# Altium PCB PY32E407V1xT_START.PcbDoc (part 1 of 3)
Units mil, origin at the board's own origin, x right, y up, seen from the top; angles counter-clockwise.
Board outline 1968.43 x 4717 mil, 2 copper layers (Top Layer, Bottom Layer), stack 21 mil thick; 210 components, 217 nets, 824 pads, 371 vias.
Unrouted connection lines stored in the file: 1.
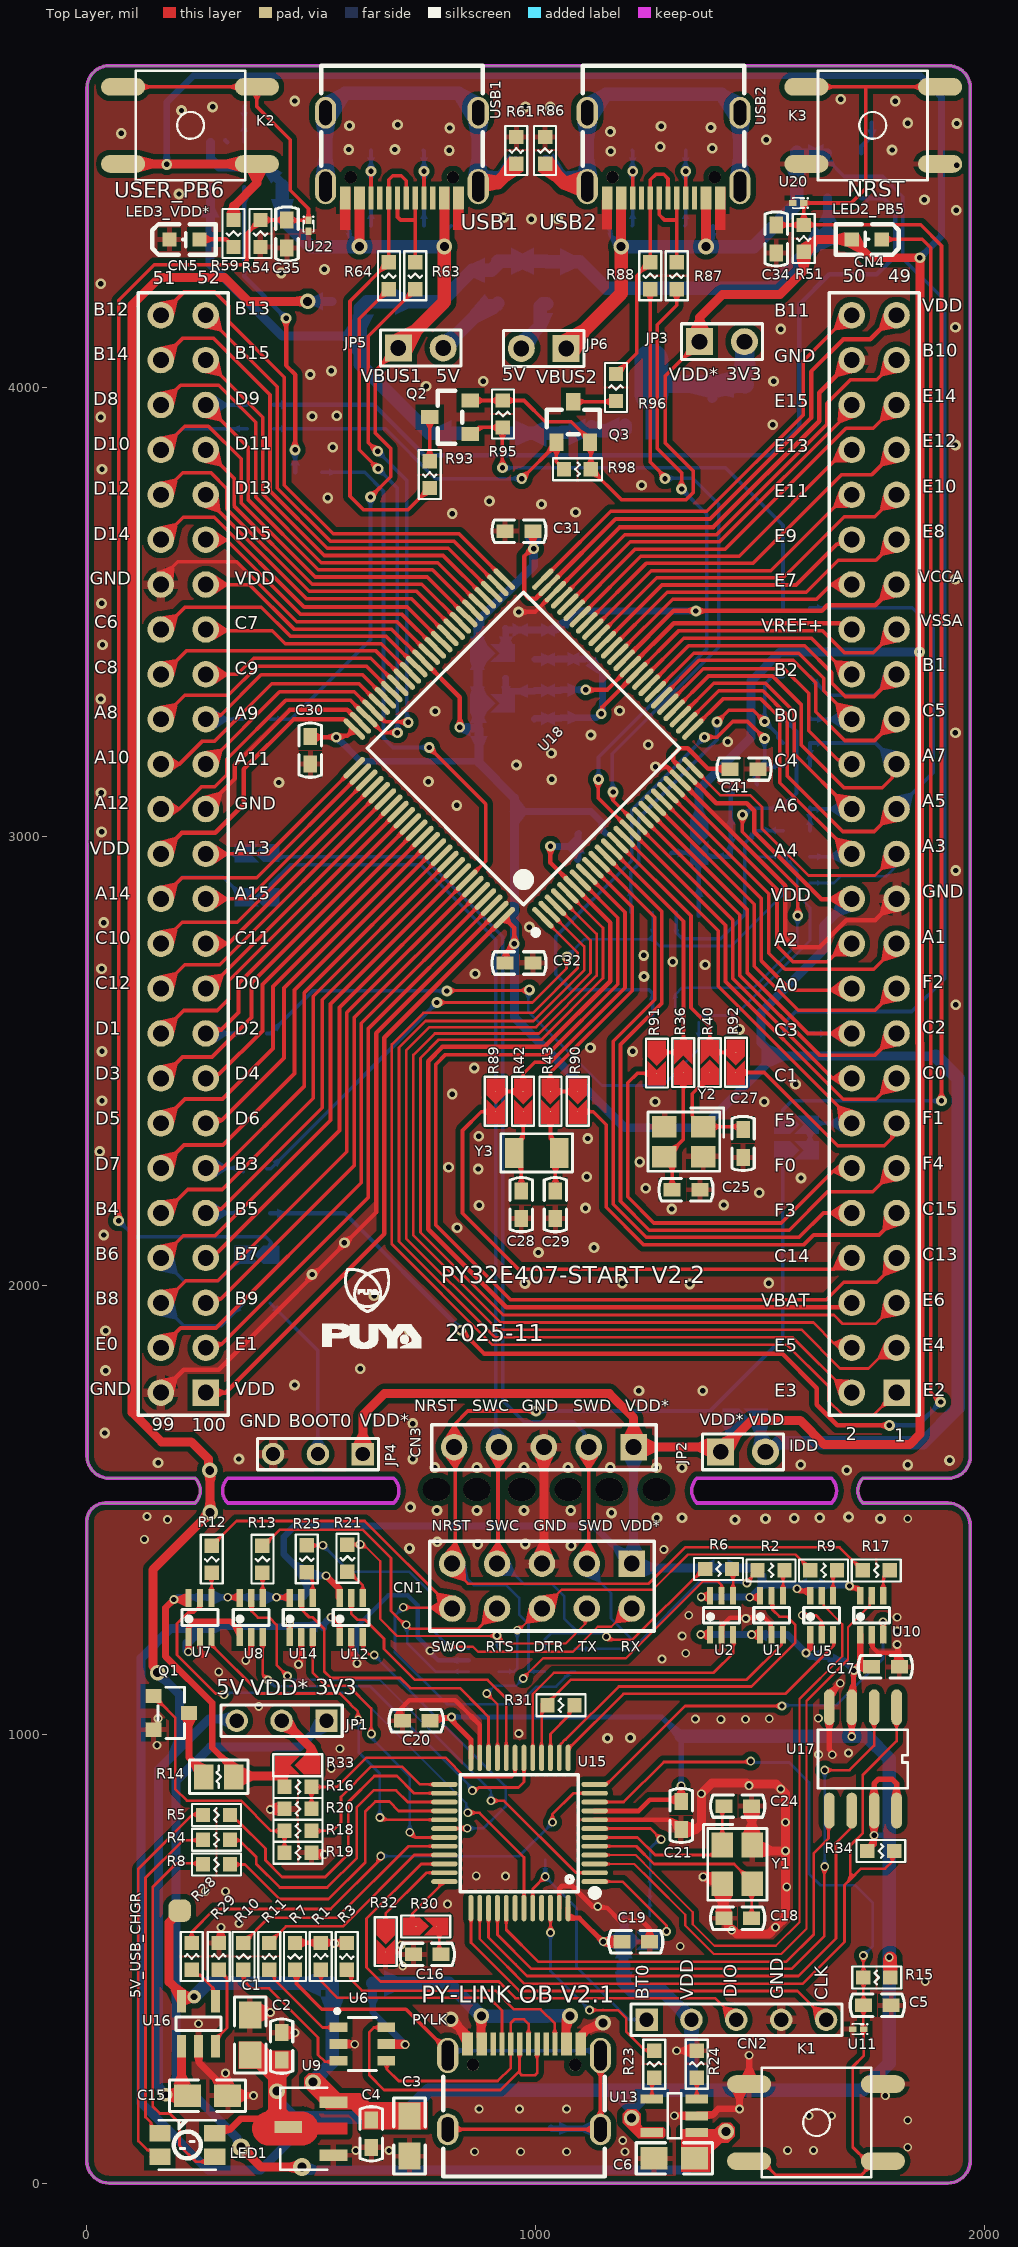
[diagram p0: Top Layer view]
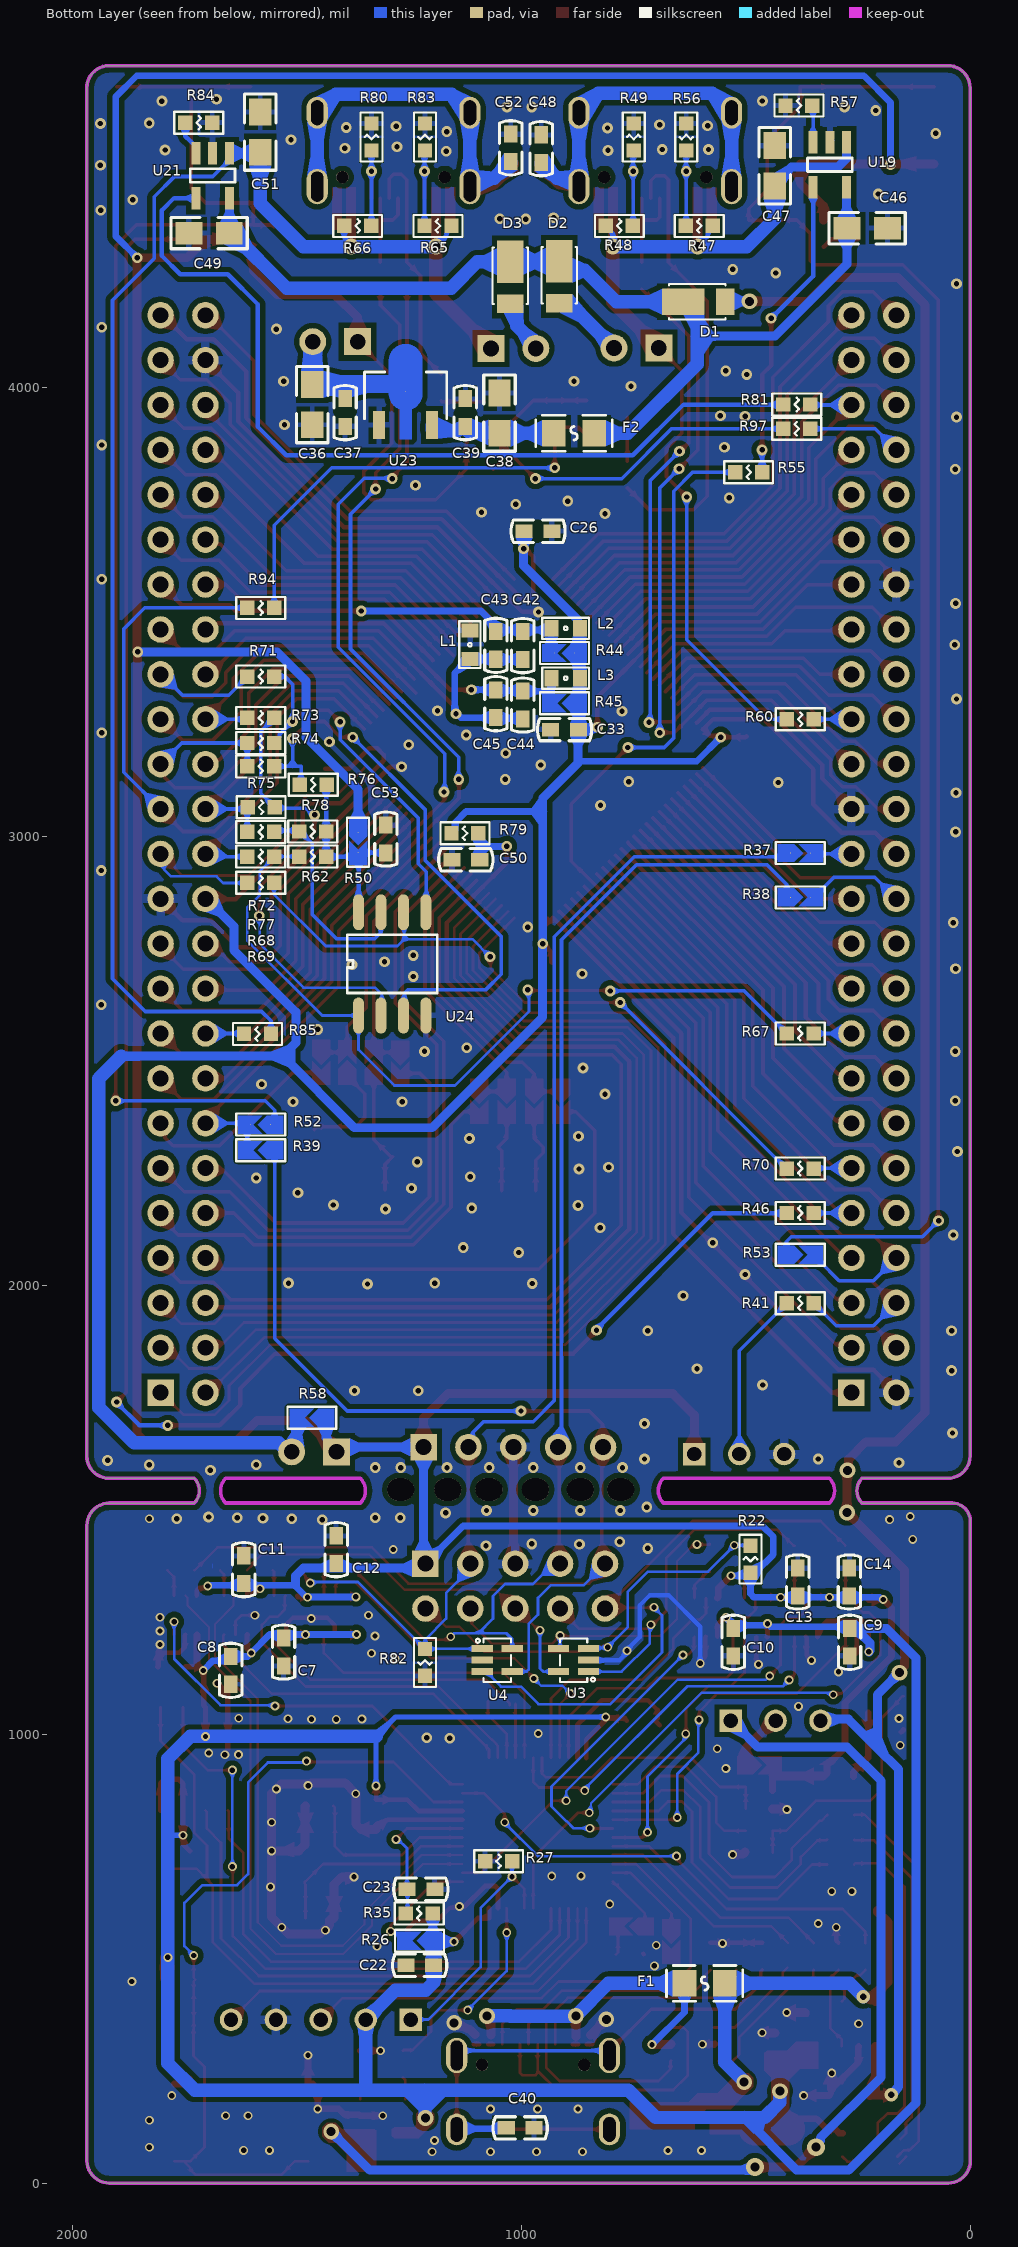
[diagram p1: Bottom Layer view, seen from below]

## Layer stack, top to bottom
Top Solder: solder mask 0.4, Solder Resist, Dk 3.5
Top Layer: signal copper 1.4
Dielectric 2: prepreg 2.8, Composite dielectric, Dk 4.1
Dielectric 1: prepreg 12.6, Composite dielectric, Dk 4.1
Dielectric 3: prepreg 2.8, Composite dielectric, Dk 4.1
Bottom Layer: signal copper 1.4
Bottom Solder: solder mask 0.4, Solder Resist, Dk 3.5

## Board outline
0,50 ccw(c50,50) 50,0 1918,0 ccw(c1918,50) 1968,50 1968,1465 ccw(c1918,1465) 1918,1515 1729,1515 cw(c1756.5,1542.5) 1729,1570 1918.43,1570 ccw(c1918.43,1620) 1968.43,1620 1968.43,4667 ccw(c1918.43,4667) 1918.43,4717 50.57,4717 ccw(c50.57,4667) 0.57,4667 0.57,1620 ccw(c50.57,1620) 50.57,1570 241.5,1570 cw(c214,1542.5) 241.5,1515 41,1515 ccw(c41,1474) 0,1474
cut-out: 1359,1515 cw(c1386.5,1542.5) 1359,1570 1659,1570 cw(c1631.5,1542.5) 1659,1515
cut-out: 314,1515 cw(c341.5,1542.5) 314,1570 684,1570 cw(c656.5,1542.5) 684,1515
cut-out: 314,1515 cw(c341.5,1542.5) 314,1570 684,1570 cw(c656.5,1542.5) 684,1515 664,1515
cut-out: 1359,1515 cw(c1386.5,1542.5) 1359,1570 1659,1570 cw(c1631.5,1542.5) 1659,1515

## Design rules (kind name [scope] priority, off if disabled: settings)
Clearance polygon [InPolygon] p1: gap=12 ignorepadtopadclearanceinfootprint=TRUE
Clearance [All] p2: gap=8 ignorepadtopadclearanceinfootprint=TRUE
HoleToHoleClearance [All] p1: gap=1 allowstackedmicrovias=TRUE
MinimumSolderMaskSliver [All] p1: minsoldermaskwidth=0
PlaneClearance [All] p1: clearance=8
PlaneConnect [All] p1: planeconnectstyle=Direct reliefexpansion=20 reliefentries=4 reliefconductorwidth=10 reliefairgap=10
PolygonConnect [All] p1: thpad.connectstyle=Relief thpad.reliefconductorwidth=20 thpad.reliefentries=4 thpad.polygonreliefangle="90 Angle" thpad.airgapwidth=10 smdpad.connectstyle=Relief smdpad.reliefconductorwidth=12 smdpad.reliefentries=4 smdpad.polygonreliefangle="90 Angle" smdpad.airgapwidth=10 via.connectstyle=Direct via.reliefconductorwidth=10 via.reliefentries=4 via.polygonreliefangle="90 Angle" via.airgapwidth=10
RoutingVias [All] p1: holewidth=28 width=50 viastyle="Through Hole" minholewidth=28 minwidth=50 maxholewidth=28 maxwidth=50
SilkToSilkClearance [All] p1: silktosilkclearance=0
SilkToSolderMaskClearance [IsPad] p1: minsilkscreentomaskgap=0 clearancetoexposedcopper=TRUE
SolderMaskExpansion [All] p1: expansion=4 istentingtop=FALSE
UnRoutedNet [All] p1: checkbadconnections=TRUE
Width [All] p1: maxlimit=100 minlimit=5 preferedwidth=8
23 further rules are at their usual default settings.

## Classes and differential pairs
component class PY32E407V1xT_USB: C46 C47 C48 C49 C51 C52 Q2 Q3 R47 R48 R49 R55 R56 R57 R60 R61 R63 R64 R65 R66 R80 R81 R83 R84 R85 R86 R87 R88 R93 R94 R95 R96 R97 R98 U19 U21 USB1 USB2
component class PY32E407V1xT_START: C25 C26 C27 C28 C29 C30 C31 C32 C33 C34 C35 C36 C37 C38 C39 C41 C42 C43 C44 C45 C50 C53 CN3 CN4 CN5 D1 D2 D3 F2 "IDD Test" JP2 JP3 JP4 JP5 JP6 K2 K3 L1 L2 L3 LED2_PB5 LED3_VDD* PF8 R36 R37 R38 R39 R40 R41 R42 R43 R44 R45 R46 R50 R51 R52 R53 R54 R58 R59 R62 R67 R68 R69 R70 R71 R72 R73 R74 R75 R76 R77 R78 R79 R89 R90 R91 R92 ss U18 U20 U22 U23 U24 Y2 Y3
component class PY32F403C1xT_LINK: 5V_USB_CHGR C1 C2 C3 C4 C5 C6 C7 C8 C9 C10 C11 C12 C13 C14 C15 C16 C17 C18 C19 C20 C21 C22 C23 C24 C40 CN1 CN2 F1 JP1 K1 LED1 PYLK Q1 R1 R2 R3 R4 R5 R6 R7 R8 R9 R10 R11 R12 R13 R14 R15 R16 R17 R18 R19 R20 R21 R22 R23 R24 R25 R26 R27 R28 R29 R30 R31 R32 R33 R34 R35 R82 ss U1 U2 U3 U4 U5 U6 U7 U8 U9 U10 U11 U12 U13 U14 U15 U16 U17 Y1

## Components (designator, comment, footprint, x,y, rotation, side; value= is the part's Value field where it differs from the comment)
5V_USB_CHGR "TP_SIN" TP_SIN 207,607 r90 top
C1 "10uF" C0805 364,330 r270 top
C2 "100nF" C0603 434,305 r270 top
C3 "10uF" C0805 719,105 r90 top
C4 "100nF" C0603 634,110 r90 top
C5 "100nF" C0603 1761,396 r180 top
C6 "10uF" C0805 1309,55 r0 top
C7 "100nF" C0603 1530,1183 r90 bottom value=104
C8 "100nF" C0603 1647.9,1142.3 r90 bottom value=104
C9 "100nF" C0603 269.2,1204.9 r90 bottom value=104
C10 "100nF" C0603 528,1204.9 r90 bottom value=104
C11 "100nF" C0603 1618.4,1366.6 r270 bottom value=104
C12 "100nF" C0603 1412.8,1411.1 r270 bottom value=104
C13 "100nF" C0603 384.5,1339.2 r270 bottom value=104
C14 "100nF" C0603 269.5,1339.2 r270 bottom value=104
C15 "10uF" C0805 269,195 r180 top
C16 "100nF" C0603 758.59,509.5 r0 top
C17 "100nF" C0603 1779,1150 r180 top value=104
C18 "22pF" C0603 1450.12,590 r0 top
C19 "100nF" C0603 1222.87,537.59 r180 top value=104
C20 "100nF" C0603 734,1030 r0 top value=104
C21 "100nF" C0603 1324.12,819 r90 top value=104
C22 "100nF" C0603 1226.74,485.58 r180 bottom value=104
C23 "100nF" C0603 1224.12,655 r0 bottom value=104
C24 "22pF" C0603 1450.12,840 r180 top
C25 "22pF" C0603 1335,2212.99 r180 top
C26 "10uF" C0603 963,3680 r0 bottom
C27 "22pF" C0603 1462,2315.99 r90 top
C28 "22pF" C0603 968,2179.5 r270 top
C29 "22pF" C0603 1044,2179.5 r90 top
C30 "100nF" C0603 498,3192 r90 top
C31 "100nF" C0603 963,3680 r0 top
C32 "100nF" C0603 963,2718 r180 top
C33 "100nF" C0603 904,3238 r180 bottom
C34 "100nF" C0603 1536,4331 r90 top
C35 "100nF" C0603 446,4342 r90 top
C36 "10uF" C0805 1466,3962 r90 bottom
C37 "100nF" C0603 1393,3944 r90 bottom
C38 "10uF" C0805 1049,3943 r270 bottom
C39 "100nF" C0603 1125,3944 r270 bottom
C40 "4.7nF" C0603 1003,123 r0 bottom
C41 "100nF" C0603 1464,3150 r180 top
C42 "1uF" C0603 997,3425 r90 bottom
C43 "100nF" C0603 1057,3425.57 r90 bottom
C44 "1uF" C0603 997,3292.5 r90 bottom
C45 "100nF" C0603 1057,3295.5 r90 bottom
C46 "10uF" C0805 230,4355 r0 bottom
C47 "10uF" C0805 436,4494 r270 bottom
C48 "4.7nF" C0603 956,4532 r270 bottom
C49 "10uF" C0805 1696,4344 r180 bottom
C50 "100nF" C0603 1124,2948 r180 bottom
C51 "10uF" C0805 1582,4569 r270 bottom
C52 "4.7nF" C0603 1024,4534 r270 bottom
C53 "100nF" C0603 1302,2994 r270 bottom value=104
CN1 "2X5P" HDR2X5 1214,1380 r180 top
CN2 "CON5" CON5 1247,364 r0 top
CN3 "Header 5" HDR1X5 1218.26,1639.56 r180 top
CN4 "2X25P" HDR2X25 1804,1761 r90 top locked
CN5 "2X25P" HDR2X25 265,1761 r90 top locked
D1 "DFLS130L-7" POWERDI-123_L2.8-W1.8-LS3.7-RD 593,4191 r180 bottom
D2 "DFLS130L-7" POWERDI-123_L2.8-W1.8-LS3.7-RD 916,4234 r270 bottom
D3 "DFLS130L-7" POWERDI-123_L2.8-W1.8-LS3.7-RD 1025,4233 r270 bottom
F1 "JK-SMD0805-050-16V" F0805 592,445 r180 bottom
F2 "JK-SMD0805-050-16V" F0805 883,3898 r0 bottom
JP1 "CON3" CON3 534,1030 r180 top
JP2 "CON2" CON2 1412,1629.13 r0 top
JP3 "CON2" CON2 1365,4102 r0 top
JP4 "CON3" CON3 615,1624.13 r180 top
JP5 "CON2" CON2 694,4088 r0 top
JP6 "CON2" CON2 1068,4087 r180 top
K1 "TS-KG02S" Switch 1626.55,134.7 r180 top
K2 "TS-KG02S" Switch 232,4583.7 r180 top
K3 "TS-KG02S" Switch 1750,4584 r0 top
L1 "BEAD" L0603 1115,3427 r90 bottom value=600R@100MHz
L2 "BEAD" L0603 901.52,3463.5 r0 bottom value=600R@100MHz
L3 "BEAD" L0603 901.52,3352.5 r0 bottom value=600R@100MHz
LED1 "MHPA3528RGBCT" LED-ARRAY-SMD_4P-L3.5-W2.8-TL 224,85 r0 top
LED2_PB5 "GREEN" 0603_LED 1723,4331 r180 top
LED3_VDD* "RED" 0603_LED 232,4329 r0 top
PYLK "KH-TYPE-C-16P" USB-C-SMD_KH-TYPE-C-16P 974.2,214.81 r0 top locked
Q1 "2302" SOT23 188.37,1047.4 r90 top value=SI2302
Q2 "2301" "SOT23 2301" 854.55,3896.6 r0 top value=SI2301
Q3 "2301" "SOT23 2301" 1046.2,3878 r270 top value=SI2301
R1 "5.1K" R0603 521.49,504.99 r270 top
R2 "27R" R0603 1524.21,1365 r180 top
R3 "5.1K" R0603 579,505 r90 top
R4 "680R" R0603 289,765 r0 top
R5 "680R" R0603 289,820 r0 top
R6 "27R" R0603 1407.39,1368.1 r180 top
R7 "1M" R0603 464,505 r90 top
R8 "680R" R0603 289,710 r0 top
R9 "27R" R0603 1641.35,1365 r180 top
R10 "27R" R0603 349,505 r90 top
R11 "27R" R0603 406.5,505 r90 top
R12 "27R" R0603 278.66,1390.08 r90 top
R13 "27R" R0603 391.3,1390.1 r90 top
R14 "100R" R0805 294,905 r0 top
R15 "10K" R0603 1759.77,458 r0 top
R16 "20K" R0603 470.52,882.61 r180 top
R17 "27R" R0603 1758.49,1365 r180 top
R18 "100R" R0603 470.53,784.78 r0 top
R19 "100K" R0603 470.52,735.88 r180 top
R20 "10K" R0603 470.53,833.69 r0 top
R21 "27R" R0603 580.63,1392.11 r90 top
R22 "4.7K" R0603 490,1390 r270 bottom
R23 "4.7K" R0603 1264,265 r270 top
R24 "16K" R0603 1359,265 r270 top
R25 "27R" R0603 490.2,1390.7 r90 top
R26 "0R" JP2_SMD 1227.34,539.83 r180 bottom
R27 "10K" R0603 1051,717.08 r0 bottom
R28 "4.7K" R0603 234,505 r270 top
R29 "16K" R0603 294,505 r270 top
R30 "0R" JP2_SMD 755.21,571.75 r180 top
R31 "680R" R0603 1056.46,1064.37 r0 top
R32 "0R" JP2_SMD 666,538 r90 top
R33 "0R" JP2_SMD 470,931 r0 top
R34 "100K" R0603 1769,740 r180 top
R35 "10K" R0603 1227.6,600.62 r180 bottom
R36 "0R" JP2_SMD 1329,2496 r270 top
R37 "100R" JP2_SMD 379,2963 r0 bottom
R38 "100R" JP2_SMD 379,2864 r0 bottom
R39 "0R" JP2_SMD 1581.01,2301 r180 bottom
R40 "0R" JP2_SMD 1388,2495.99 r270 top
R41 "10K" R0603 379,1960 r180 bottom
R42 "0R" JP2_SMD 972,2410 r90 top
R43 "0R" JP2_SMD 1033,2410 r90 top
R44 "0R/NC" JP2_SMD 904,3408.5 r180 bottom
R45 "0R/NC" JP2_SMD 904,3296.5 r180 bottom
R46 "680R" R0603 379,2161 r180 bottom
R47 "56K/NC" R0603 604,4359.99 r180 bottom
R48 "56K/NC" R0603 782,4360 r0 bottom
R49 "5.1K" R0603 750,4558 r270 bottom
R50 "0R" JP2_SMD 1363.97,2987.03 r90 bottom
R51 "10K" R0603 1597,4332 r90 top
R52 "0R" JP2_SMD 1581.01,2358 r180 bottom
R53 "0R" JP2_SMD 379,2068 r0 bottom
R54 "1.5K" R0603 387,4343 r90 top
R55 "4.7K" R0603 494,3811 r180 bottom
R56 "5.1K" R0603 633,4558.01 r90 bottom
R57 "16K" R0603 382,4628 r180 bottom
R58 "0R" JP2_SMD 1467,1705 r180 bottom
R59 "680R" R0603 327,4343 r90 top
R60 "1K" R0603 379,3261 r0 bottom
R61 "1M" R0603 957,4528 r90 top
R62 "100K" R0603 1465,2954.99 r180 bottom
R63 "22R" R0603 732,4249 r90 top
R64 "22R" R0603 673,4249 r90 top
R65 "56K/NC" R0603 1186,4360 r180 bottom
R66 "56K/NC" R0603 1365,4360 r0 bottom
R67 "0R" R0603 379,2561 r180 bottom
R68 "0R/NC" R0603 1581.01,2955 r0 bottom
R69 "0R" R0603 1581.01,2897 r0 bottom
R70 "0R/NC" R0603 379,2260 r180 bottom
R71 "0R" R0603 1581.01,3356 r0 bottom
R72 "0R/NC" R0603 1580,3065 r0 bottom
R73 "0R" R0603 1581.01,3264 r0 bottom
R74 "0R/NC" R0603 1581.01,3208 r0 bottom
R75 "0R" R0603 1581.01,3156 r0 bottom
R76 "0R/NC" R0603 1464,3115 r180 bottom
R77 "0R" R0603 1581,3010 r0 bottom
R78 "0R/NC" R0603 1465,3011 r180 bottom
R79 "0R" R0603 1126,3007 r180 bottom
R80 "5.1K" R0603 1334,4558 r270 bottom
R81 "4.7K" R0603 387,3962 r0 bottom
R82 "1M" R0603 1215,1160 r90 bottom
R83 "5.1K" R0603 1215,4558.01 r90 bottom
R84 "16K" R0603 1719,4590 r0 bottom
R85 "1K" R0603 1588,2560 r180 bottom
R86 "1M" R0603 1021,4528 r90 top
R87 "22R" R0603 1314,4249 r90 top
R88 "22R" R0603 1255,4249 r90 top
R89 "0R" JP2_SMD 911,2410 r90 top
R90 "0R" JP2_SMD 1094,2410 r90 top
R91 "0R" JP2_SMD 1270,2495 r90 top
R92 "0R" JP2_SMD 1446,2497 r90 top
R93 "1.5K" R0603 764,3806 r90 top
R94 "100" R0603 1581.01,3509 r0 bottom
R95 "100K" R0603 927,3941 r270 top
R96 "1.5K" R0603 1179,4000 r270 top
R97 "100" R0603 387,3908 r180 bottom
R98 "100K" R0603 1093,3818 r180 top
U1 "74LVC1T45DW" SOT363 1525.64,1265 r0 top
U2 "74LVC1T45DW" SOT363 1414.21,1265 r0 top
U3 "ESD_6V1" ESD_SOT323-5L 884,1165 r90 bottom value=ESDALC6V1W5
U4 "ESD_6V1" ESD_SOT323-5L 1054,1165 r270 bottom value=ESDALC6V1W5
U5 "74LVC1T45DW" SOT363 1637.06,1265 r0 top locked
U6 "USBLC6-2SC6" SOT23-6 614,310 r90 top
U7 "74LVC1T45DW" SOT363 252.55,1260 r0 top locked
U8 "74LVC1T45DW" SOT363 366.26,1260 r0 top
U9 "LM1117-3.3" LM1117-3.3#1 549.38,62.1 r0 top
U10 "74LVC1T45DW" SOT363 1748.49,1265 r0 top
U11 "ESD-TRANSIL" ESD_ST0201 1718.24,343 r180 top value=ESDALC6V1-1U2
U12 "74LVC1T45DW" SOT363 589.12,1260 r0 top
U13 "MT9700" SOT23-5 1309,150 r90 top
U14 "74LVC1T45DW" SOT363 477.69,1260 r0 top
U15 "PY32F403C1xT" LQFP-48_L7.0-W7.0-P0.50-LS9.0-BL 964,780 r90 top locked
U16 "MT9700" SOT23-5 249,355 r0 top
U17 "P25Q64SH" SOP-8P 1729,945 r180 top value=SST25VF020B
U18 "PY32E407Vx" LQFP-100_L14.0-W14.0-P0.50-LS16.0-BL 973,3196 r45 top locked
U19 "MT9700" SOT23-5 313,4496 r0 bottom
U20 "ESD-TRANSIL" ESD_ST0201 1585,4411 r180 top value=ESDALC6V1-1U2
U21 "MT9700" SOT23-5 1688,4472 r0 bottom
U22 "ESD-TRANSIL" ESD_ST0201 494,4360 r270 top value=ESDALC6V1-1U2
U23 "LM1117-3.3" LM1117-3.3#2 1317.4,3916.16 r270 bottom
U24 "P25Q64SH" SOP-8P 1288,2716 r180 bottom value=SST25VF020B
USB1 "KH-TYPE-C-16P" USB-C-SMD_KH-TYPE-C-16P 702,4517 r180 top
USB2 "KH-TYPE-C-16P" USB-C-SMD_KH-TYPE-C-16P 1285,4517 r180 top
Y1 "24MHz" CRYSTAL-SMD_4P-L3.2-W2.5-BL 1449.12,710 r270 top
Y2 "24MHz" CRYSTAL-SMD_4P-L3.2-W2.5-BL 1330,2319.99 r180 top
Y3 "32.768KHz" CRYSTAL-SMD_L3.2-W1.5-1 1002,2295 r180 top value=X503225MSB2GI

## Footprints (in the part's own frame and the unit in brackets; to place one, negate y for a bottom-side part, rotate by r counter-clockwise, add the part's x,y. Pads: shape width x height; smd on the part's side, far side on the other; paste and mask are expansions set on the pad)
0603_LED [mil]
  rect 31.5x31.5 smd: 1(19,1) 2(-48,1)
  silkscreen extent -86,-33 55,35
C0603 [mil]
  rect 38x30 smd: 1(-31,0) 2(31,0)
  silkscreen extent -60,-25 60,25
C0805 [mil]
  rect 60x50 smd: 1(-45,0) 2(45,0)
  silkscreen extent -85,-35 85,35
CON2 [mil]
  rect 60x60 hole 35: 1(0,0)
  round 60 hole 35: 2(100,0)
  silkscreen extent -40,-40 140,40
CON3 [mil]
  rect 50x50 hole 32: 1(0,0)
  round 50 hole 32: 2(100,0) 3(200,0)
  silkscreen extent -35,-35 235,35
CON5 [mil]
  rect 50x50 hole 32: 1(0,0)
  round 50 hole 32: 2(100,0) 3(200,0) 4(300,0) 5(400,0)
  silkscreen extent -35,-35 435,35
CRYSTAL-SMD_4P-L3.2-W2.5-BL [mm]
  rect 1.4x1.2 smd: 1(-1.1,-0.85) 2(1.1,-0.85) 3(1.1,0.85) 4(-1.1,0.85)
  silkscreen extent -2.26,-1.91 2.03,1.68
CRYSTAL-SMD_L3.2-W1.5-1 [mm]
  rect 1.05x1.7 smd: 1(-1.275,0) 2(1.275,0)
  silkscreen extent -2.03,-1.08 2.03,1.08
ESD_SOT323-5L [mm]
  rect 0.4x1.2 smd mask+0.05: 1(-0.65,-0.85) 2(0,-0.85) 3(0.65,-0.85) 4(0.65,0.85) 5(-0.65,0.85)
  silkscreen extent -1.23,-1.21 1.23,0.77, body extent -1.15,-1.05 1.15,1.05, height 1.1
ESD_ST0201 [mm]
  rect 0.425x0.33 smd mask+0.05: 1(-0.312,0) 2(0.312,0)
  silkscreen extent -0.55,-0.3 0.33,0.3, body extent -0.34,-0.18 0.34,0.18, height 0.34
F0805 [mm]
  rect 1.335x1.5 smd paste-100 mask+0.051: 1(-1.142,0) 2(1.142,0)
  silkscreen extent -2.16,-1.02 2.16,1.02
HDR1X5 [mm] "Connector; Header; 5 Position"
  rect 1.5x1.5 hole 0.9: 1(0,0)
  round 1.5 hole 0.9: 2(2.54,0) 3(5.08,0) 4(7.62,0) 5(10.16,0)
  silkscreen extent -1.27,-1.27 11.43,1.27
HDR2X5 [mm] "Connector; Header; 4x2 Position"
  rect 1.5x1.5 hole 0.9: 1(0,0)
  round 1.5 hole 0.9: 2(0,2.54) 3(2.54,0) 4(2.54,2.54) 5(5.08,0) 6(5.08,2.54) 7(7.62,0) 8(7.62,2.54) 9(10.16,0) 10(10.16,2.54)
  silkscreen extent -1.27,-1.27 11.43,3.81
HDR2X25 [mm] "Connector; Header; 25x2 Position"
  rect 1.5x1.5 hole 0.9: 1(0,0)
  round 1.5 hole 0.9: 2(0,2.54) 3(2.54,0) 4(2.54,2.54) 5(5.08,0) 6(5.08,2.54) 7(7.62,0) 8(7.62,2.54) 9(10.16,0) 10(10.16,2.54) 11(12.7,0) 12(12.7,2.54) 13(15.24,0) 14(15.24,2.54) 15(17.78,0) 16(17.78,2.54) 17(20.32,0) 18(20.32,2.54) 19(22.86,0) 20(22.86,2.54) 21(25.4,0) 22(25.4,2.54) 23(27.94,0) 24(27.94,2.54) 25(30.48,0) 26(30.48,2.54) 27(33.02,0) 28(33.02,2.54) 29(35.56,0) 30(35.56,2.54) 31(38.1,0) 32(38.1,2.54) 33(40.64,0) 34(40.64,2.54) 35(43.18,0) 36(43.18,2.54) 37(45.72,0) 38(45.72,2.54) 39(48.26,0) 40(48.26,2.54) 41(50.8,0) 42(50.8,2.54) 43(53.34,0) 44(53.34,2.54) 45(55.88,0) 46(55.88,2.54) 47(58.42,0) 48(58.42,2.54) 49(60.96,0) 50(60.96,2.54)
  silkscreen extent -1.27,-1.27 62.23,3.81
JP2_SMD [mil]
  round 1 smd: 1(21.75,0) 2(-23.03,0.03)
  Top Layer region: -6.25,0 13.75,20 49.75,20 49.75,-20 49.75,-20 13.75,-20
  Top Layer region: -49.77,20.03 -49.77,20.03 3.72,20.03 -16.28,0.03 3.72,-19.98 -49.78,-19.98 -49.78,-19.98
  silkscreen extent -55,-25 54,25
L0603 [mm]
  rect 0.8x0.95 smd mask+0.05: 1(-0.8,0) 2(0.8,0)
  silkscreen extent -1.33,-0.6 1.33,0.6, body extent -0.87,-0.47 0.87,0.47, height 0.95
LED-ARRAY-SMD_4P-L3.5-W2.8-TL [mm]
  rect 1.2x0.95 smd: 1(1.55,0.665) 2(1.55,-0.665) 3(-1.55,-0.665) 4(-1.55,0.665)
  silkscreen extent -1.6,-1.4 1.6,1.4
LM1117-3.3#1 [mm]
  rect 1.575x0.672 smd: 1(0,0) 2(-2.55,1.598) 3(0,3)
  Top Layer region: -3.64,2.459 -1.785,2.459 -1.741,2.458 -1.696,2.455 -1.652,2.449 -1.608,2.442 -1.565,2.433 -1.522,2.421 -1.479,2.408 -1.437,2.393 -1.396,2.375 -1.356,2.356 -1.317,2.335 -1.279,2.312 -1.241,2.288 -1.206,2.261 -1.171,2.233 -1.138,2.204 -1.106,2.173 -1.075,2.14 -1.047,2.106 -1.019,2.071 -0.994,2.034 -0.97,1.996 -0.948,1.958 -0.928,1.918 -0.91,1.839 0.788,1.839 0.788,1.179 -0.91,1.179 -0.928,1.099 -0.948,1.06 -0.97,1.021 -0.994,0.983 -1.019,0.947 -1.047,0.911 -1.075,0.877 -1.106,0.845 -1.138,0.814 -1.171,0.784 -1.206,0.756 -1.241,0.73 -1.279,0.705 -1.317,0.682 -1.356,0.661 -1.396,0.642 -1.437,0.625 -1.479,0.609 -1.522,0.596 -1.565,0.585 -1.608,0.575 -1.652,0.568 -1.696,0.563 -1.741,0.56 -1.785,0.559 -3.64,0.559 -3.684,0.56 -3.728,0.563 -3.773,0.568 -3.817,0.575 -3.86,0.585 -3.903,0.596 -3.946,0.609 -3.988,0.625 -4.029,0.642 -4.069,0.661 -4.108,0.682 -4.146,0.705 -4.183,0.73 -4.219,0.756 -4.254,0.784 -4.287,0.814 -4.319,0.845 -4.349,0.877 -4.378,0.911 -4.405,0.947 -4.431,0.983 -4.455,1.021 -4.477,1.06 -4.497,1.099 -4.515,1.14 -4.531,1.181 -4.546,1.224 -4.558,1.266 -4.568,1.31 -4.577,1.353 -4.583,1.398 -4.587,1.442 -4.589,1.486 -4.589,1.531 -4.587,1.575 -4.583,1.62 -4.577,1.664 -4.568,1.708 -4.558,1.751 -4.546,1.794 -4.531,1.836 -4.515,1.877 -4.497,1.918 -4.477,1.958 -4.455,1.996 -4.431,2.034 -4.405,2.071 -4.378,2.106 -4.349,2.14 -4.319,2.173 -4.287,2.204 -4.254,2.233 -4.219,2.261 -4.183,2.288 -4.146,2.312 -4.108,2.335 -4.069,2.356 -4.029,2.375 -3.988,2.393 -3.946,2.408 -3.903,2.421 -3.86,2.433 -3.817,2.442 -3.773,2.449 -3.728,2.455 -3.684,2.458
  silkscreen extent -3.01,-0.83 -0.35,3.83
LM1117-3.3#2 [mm]
  rect 1.575x0.672 smd: 1(0,0) 3(0,3)
  round 0.025 smd: 2(-1.901,1.509)
  Top Layer region: -3.64,2.459 -1.785,2.459 -1.741,2.458 -1.696,2.455 -1.652,2.449 -1.608,2.442 -1.565,2.433 -1.522,2.421 -1.479,2.408 -1.437,2.393 -1.396,2.375 -1.356,2.356 -1.317,2.335 -1.279,2.312 -1.241,2.288 -1.206,2.261 -1.171,2.233 -1.138,2.204 -1.106,2.173 -1.075,2.14 -1.047,2.106 -1.019,2.071 -0.994,2.034 -0.97,1.996 -0.948,1.958 -0.928,1.918 -0.91,1.839 0.788,1.839 0.788,1.179 -0.91,1.179 -0.928,1.099 -0.948,1.06 -0.97,1.021 -0.994,0.983 -1.019,0.947 -1.047,0.911 -1.075,0.877 -1.106,0.845 -1.138,0.814 -1.171,0.784 -1.206,0.756 -1.241,0.73 -1.279,0.705 -1.317,0.682 -1.356,0.661 -1.396,0.642 -1.437,0.625 -1.479,0.609 -1.522,0.596 -1.565,0.585 -1.608,0.575 -1.652,0.568 -1.696,0.563 -1.741,0.56 -1.785,0.559 -3.64,0.559 -3.684,0.56 -3.728,0.563 -3.773,0.568 -3.817,0.575 -3.86,0.585 -3.903,0.596 -3.946,0.609 -3.988,0.625 -4.029,0.642 -4.069,0.661 -4.108,0.682 -4.146,0.705 -4.183,0.73 -4.219,0.756 -4.254,0.784 -4.287,0.814 -4.319,0.845 -4.349,0.877 -4.378,0.911 -4.405,0.947 -4.431,0.983 -4.455,1.021 -4.477,1.06 -4.497,1.099 -4.515,1.14 -4.531,1.181 -4.546,1.224 -4.558,1.266 -4.568,1.31 -4.577,1.353 -4.583,1.398 -4.587,1.442 -4.589,1.486 -4.589,1.531 -4.587,1.575 -4.583,1.62 -4.577,1.664 -4.568,1.708 -4.558,1.751 -4.546,1.794 -4.531,1.836 -4.515,1.877 -4.497,1.918 -4.477,1.958 -4.455,1.996 -4.431,2.034 -4.405,2.071 -4.378,2.106 -4.349,2.14 -4.319,2.173 -4.287,2.204 -4.254,2.233 -4.219,2.261 -4.183,2.288 -4.146,2.312 -4.108,2.335 -4.069,2.356 -4.029,2.375 -3.988,2.393 -3.946,2.408 -3.903,2.421 -3.86,2.433 -3.817,2.442 -3.773,2.449 -3.728,2.455 -3.684,2.458
  silkscreen extent -3.01,-0.83 -0.35,3.83
LQFP-48_L7.0-W7.0-P0.50-LS9.0-BL [mm]
  oval 0.27x1.5 smd mask+0.05: 1(-2.75,-4.25) 2(-2.25,-4.25) 3(-1.75,-4.25) 4(-1.25,-4.25) 5(-0.75,-4.25) 6(-0.25,-4.25) 7(0.25,-4.25) 8(0.75,-4.25) 9(1.25,-4.25) 10(1.75,-4.25) 11(2.25,-4.25) 12(2.75,-4.25) 25(2.75,4.25) 26(2.25,4.25) 27(1.75,4.25) 28(1.25,4.25) 29(0.75,4.25) 30(0.25,4.25) 31(-0.25,4.25) 32(-0.75,4.25) 33(-1.25,4.25) 34(-1.75,4.25) 35(-2.25,4.25) 36(-2.75,4.25)
  oval 1.5x0.27 smd mask+0.05: 13(4.25,-2.75) 14(4.25,-2.25) 15(4.25,-1.75) 16(4.25,-1.25) 17(4.25,-0.75) 18(4.25,-0.25) 19(4.25,0.25) 20(4.25,0.75) 21(4.25,1.25) 22(4.25,1.75) 23(4.25,2.25) 24(4.25,2.75) 37(-4.25,2.75) 38(-4.25,2.25) 39(-4.25,1.75) 40(-4.25,1.25) 41(-4.25,0.75) 42(-4.25,0.25) 43(-4.25,-0.25) 44(-4.25,-0.75) 45(-4.25,-1.25) 46(-4.25,-1.75) 47(-4.25,-2.25) 48(-4.25,-2.75)
  silkscreen extent -3.59,-4.46 3.3,3.34
LQFP-100_L14.0-W14.0-P0.50-LS16.0-BL [mm]
  oval 0.3x1.6 smd: 1(-6,-7.55) 2(-5.5,-7.55) 3(-5,-7.55) 4(-4.5,-7.55) 5(-4,-7.55) 6(-3.5,-7.55) 7(-3,-7.55) 8(-2.5,-7.55) 9(-2,-7.55) 10(-1.5,-7.55) 11(-1,-7.55) 12(-0.5,-7.55) 13(0,-7.55) 14(0.5,-7.55) 15(1,-7.55) 16(1.5,-7.55) 17(2,-7.55) 18(2.5,-7.55) 19(3,-7.55) 20(3.5,-7.55) 21(4,-7.55) 22(4.5,-7.55) 23(5,-7.55) 24(5.5,-7.55) 25(6,-7.55) 51(6,7.55) 52(5.5,7.55) 53(5,7.55) 54(4.5,7.55) 55(4,7.55) 56(3.5,7.55) 57(3,7.55) 58(2.5,7.55) 59(2,7.55) 60(1.5,7.55) 61(1,7.55) 62(0.5,7.55) 63(0,7.55) 64(-0.5,7.55) 65(-1,7.55) 66(-1.5,7.55) 67(-2,7.55) 68(-2.5,7.55) 69(-3,7.55) 70(-3.5,7.55) 71(-4,7.55) 72(-4.5,7.55) 73(-5,7.55) 74(-5.5,7.55) 75(-6,7.55)
  oval 1.6x0.3 smd: 26(7.55,-6) 27(7.55,-5.5) 28(7.55,-5) 29(7.55,-4.5) 30(7.55,-4) 31(7.55,-3.5) 32(7.55,-3) 33(7.55,-2.5) 34(7.55,-2) 35(7.55,-1.5) 36(7.55,-1) 37(7.55,-0.5) 38(7.55,0) 39(7.55,0.5) 40(7.55,1) 41(7.55,1.5) 42(7.55,2) 43(7.55,2.5) 44(7.55,3) 45(7.55,3.5) 46(7.55,4) 47(7.55,4.5) 48(7.55,5) 49(7.55,5.5) 50(7.55,6) 76(-7.55,6) 77(-7.55,5.5) 78(-7.55,5) 79(-7.55,4.5) 80(-7.55,4) 81(-7.55,3.5) 82(-7.55,3) 83(-7.55,2.5) 84(-7.55,2) 85(-7.55,1.5) 86(-7.55,1) 87(-7.55,0.5) 88(-7.55,0) 89(-7.55,-0.5) 90(-7.55,-1) 91(-7.55,-1.5) 92(-7.55,-2) 93(-7.55,-2.5) 94(-7.55,-3) 95(-7.55,-3.5) 96(-7.55,-4) 97(-7.55,-4.5) 98(-7.55,-5) 99(-7.55,-5.5) 100(-7.55,-6)
  silkscreen extent -7.03,-8 6.25,6.25
POWERDI-123_L2.8-W1.8-LS3.7-RD [mm]
  rect 2.4x1.5 smd: 1(-1.187,0)
  rect 1.05x1.5 smd: 2(1.187,0)
  silkscreen extent -2,-1 1.2,1
R0603 [mil]
  rect 32x32 smd: 1(-30,0) 2(30,0)
  silkscreen extent -55,-24 54,25
R0805 [mm]
  rect 1.1x1.4 smd: 1(-0.85,0) 2(0.85,0)
  silkscreen extent -1.65,-0.95 1.65,0.95
SOP-8P [mil]
  oval 24x80 smd: 1(-75,-115) 2(-25,-115) 3(25,-115) 4(75,-115) 5(75,115) 6(25,115) 7(-25,115) 8(-75,115)
  silkscreen extent -100,-65 100,65
SOT23 [mm]
  rect 0.8x0.9 smd: 1(0.95,1) 2(-0.95,1) 3(0,-1)
  silkscreen extent -1.45,-0.75 1.45,0.75
"SOT23 2301" [mm]
  rect 1x0.8 smd mask+0.051: 1(0,0) 2(0,1.9) 3(-2.3,0.95)
  silkscreen extent -1.85,-0.55 -0.45,2.45
SOT23-5 [mil]
  rect 20x50 smd: 1(-37.5,-50) 2(0,-50) 3(37.5,-50) 4(37.5,50) 5(-37.5,50)
  silkscreen extent -50,-15 50,15
SOT23-6 [mm]
  rect 0.55x1 smd: 1(0.95,1.35) 2(0,1.35) 3(-0.95,1.35) 4(-0.95,-1.35) 5(0,-1.35) 6(0.95,-1.35)
  silkscreen extent -1.5,-0.8 1.96,1.52
SOT363 [mm]
  rect 0.35x1 smd: 1(-0.65,-1.1) 2(0,-1.1) 3(0.65,-1.1) 4(0.65,1.1) 5(0,1.1) 6(-0.65,1.1)
  silkscreen extent -1.02,-0.45 1.02,0.45, body extent -1,-1.1 1,1.16, height 1
Switch [mm]
  oval 2.5x1 smd: 1(-3.734,2.177) 2(3.835,2.177) 3(-3.734,-2.184) 4(3.835,-2.184)
  silkscreen extent -3.08,-3.1 3.12,3.09, body extent -4.48,-3 4.52,3, height 8.95
TP_SIN [mil]
  rrect60% 50x50 smd: 1(0,0)
USB-C-SMD_KH-TYPE-C-16P [mm]
  oval 1.2x2 hole 0.7 slot 1.7 at 90 deg: 1(-4.32,1.765) 2(4.32,1.765)
  oval 1.2x1.8 hole 0.7 slot 1.4 at 90 deg: 3(-4.32,-2.415) 4(4.32,-2.415)
  rect 0.3x1.3 smd: A1(-3.35,2.415) A4(-2.55,2.415) A5(-1.25,2.415) A6(-0.25,2.415) A7(0.25,2.415) A8(1.25,2.415) A9(2.55,2.415) A12(3.35,2.415) B1(3.05,2.415) B4(2.25,2.415) B5(1.75,2.415) B6(0.75,2.415) B7(-0.75,2.415) B8(-1.75,2.415) B9(-2.25,2.415) B12(-3.05,2.415)
  round 0.7 hole 0.7 unplated: ""(-2.89,1.235) ""(2.89,1.235)
  silkscreen extent -4.57,-5.08 4.57,0.57

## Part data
C1 C3 C6 C15 C36 C38 C42 C44 C46 C47 C49 C51: library part C0805
C2 C4 C5 C16 C18 C24 C25 C26 C27 C30 C31 C32 C33 C34 C35 C37 C39 C40 C41 C43 C45 C48 C50 C52: library part C0603
C7 C8 C9 C10 C11 C12 C13 C14 C17 C19 C20 C21 C22 C23 C53: library part 贴片高压陶瓷电容, "Capacitor (Semiconductor SIM Model)"
C28 C29: library part Cap, "Capacitor"
CN1: Color=黑色, Current Rating (Max)=-, JLCPCB Part Class="Extended Part", LCSC Part Name="间距:2.54mm 2x5P 直插 方针", Manufacturer=XFCN(兴飞), Manufacturer Part=PZ254V-12-10P, Operating Temperature Range=-40℃~+105℃
CN3: "Header, 5-Pin"
CN4 CN5: library part "Header 25X2", "Header, 25-Pin, Dual row"
D1 D2 D3: Average Rectified Current (Io)=1A, Forward Voltage (Vf@If)=310mV@1A, JLCPCB Part Class="Extended Part", LCSC Part Name="电压:30V 电流:1A", Manufacturer=DIODES(美台), Reverse Voltage (Vr)=30V
F1 F2: Current - Max=100A, Hold Current=500mA, JLCPCB Part Class="Extended Part", LCSC Part Name="6V 0.5A 贴片自恢复", Manufacturer=JK(金科), Operating Temperature=-40℃~+85℃, Power Dissipation=600mW, Resistance - Initial (Ri) (Min)=150mΩ, Resistance - Post Trip (R1) (Max)=850mΩ, Trip Current=1A, Voltage - Max=6V
JP2 JP3 JP5 JP6: library part CON2_DIP
K1 K2 K3: library part TS-KG02S-AT50F, Actuator/Cap Color=黑色, Contact Current=50mA, Insulation Resistance=100MΩ, JLCPCB Part Class="Extended Part", LCSC Part Name="6*6*5mm 立贴 轻触开关", Manufacturer=HANBO(汉博), Operating Force=250gf, Voltage Rating (DC)=12V
L1 L2 L3: "SMD Chip ferrite bead, 600R@100MHz +/-25%, 350mA, 500mohm DC, 0603, T=0.8mm", Manufacturer=TAI-TECH, Manufacturer_Part_Number=FCM1608KF-601T03
LED1: JLCPCB Part Class=扩展库, LCSC Part Name=RGB三色, Manufacturer=MEIHUA(美华)
LED2_PB5 LED3_VDD*: library part PDI-E803_Dup1
PYLK USB1 USB2: BOM_JLCPCB Part Class="Extended Part", BOM_Manufacturer="Shenzhen Kinghelm Elec"
Q1: library part "MOSFET N", "MOSFET N"
Q2 Q3: library part "MOSFET P", "MOSFET P"
R1 R2 R3 R4 R5 R6 R7 R8 R9 R10 R11 R12 R13 R15 R16 R17 R18 R19 R20 R21 R22 R23 R24 R25 R26 R27 R28 R29 R30 R31 R32 R33 R34 R35 R36 R37 R38 R39 R40 R41 R42 R43 R44 R45 R46 R47 R48 R49 R50 R51 R52 R53 R54 R55 R56 R57 R58 R59 R60 R61 R62 R63 R64 R65 R66 R67 R68 R69 R70 R71 R72 R73 R74 R75 R76 R77 R78 R79 R80 R81 R82 R83 R84 R85 R86 R87 R88 R89 R90 R91 R92 R93 R94 R95 R96 R97 R98: library part R0603
R14: library part R0805
U3 U4: library part ESDALC6V1W5, "Dual Transil array for ESD protection", Manufacturer=STMICROELECTRONICS
U11 U20 U22: "ESD protection 6V1", Manufacturer=STMICROELECTRONICS, Manufacturer_Part_Number=ESDALC6V1-1U2
U15: "LQFP48", BOM_Manufacturer=PUYA(普冉)
U17 U24: library part SST25VF010, "SST25VF010"
U18: "LQFP100", BOM_Manufacturer=PUYA(普冉)
Y1 Y2: library part ABM8AIG-24.000MHZ-82Z-T, "±20ppm , 12.5pF , T_use: -40°C~125°C", Equivalent Series Resistance (ESR)=50Ω, External load capacitor=8pF, Frequency Stability(Full temperature range)=±50ppm, JLCPCB Part Class="Extended Part", LCSC Part Name="24MHz ±20ppm 8pF", Manufacturer=ABRACON, Normal temperature Frequency Tolerance=±20ppm, Operating Temperature=-40℃~+125℃
Y3: library part CRYSTAL_1, "Crystal"

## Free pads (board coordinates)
  oval 60x50 hole 50 slot 60 at 0 deg unplated: 1(779,1545) 1(869,1545) 1(969,1545) 1(1072.55,1545) 1(1164,1545) 1(1269,1545)

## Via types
v1: diameter 24, hole 12, Top Layer to Bottom Layer, tented both sides, 208 vias
v2: diameter 19.68, hole 11.81, Top Layer to Bottom Layer, tented both sides, 106 vias
v3: diameter 19.68, hole 11.81, Top Layer to Bottom Layer, 37 vias
v4: diameter 35, hole 20, Top Layer to Bottom Layer, tented both sides, 16 vias
v5: diameter 30, hole 15, Top Layer to Bottom Layer, tented both sides, 2 vias
v6: diameter 40, hole 20, Top Layer to Bottom Layer, tented both sides, 2 vias

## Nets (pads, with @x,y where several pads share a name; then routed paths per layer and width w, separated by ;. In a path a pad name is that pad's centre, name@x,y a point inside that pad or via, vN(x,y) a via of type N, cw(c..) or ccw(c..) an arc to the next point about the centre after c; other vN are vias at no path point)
3.3V_OUT_EN: R23.1 U15.46 | length 462.5
  Top Layer w6: U15.46@1032.9,612.68 1032.95,612.63 v2(1033,558) v2(1033,558) ; v2(1119.8,385.43) 1149.93,385.5 cw(c1150,357) 1150.18,385.5 1183.63,385.37 1201.5,367.5 1201.5,337.5 1242.51,296.49 1262.51,296.49 R23.1@1264,295
  Bottom Layer w6: v2(1033,558) 1033,472.23 v2(1119.8,385.43)
3V3: C36.2 C37.2 JP3.2 U23.2 | length 351.6
  Bottom Layer w20: C37.2@1393,3975 1395,3977 1395,4007.7
  Bottom Layer w40: 1252,3997 U23.2@1258,3991 1274.7,4007.7 1395,4007.7 C36.2@1465.3,4007.7 ; JP3.2@1465,4102 1465.5,4101.5 1465.5,4007.5 C36.2@1466,4007
3V3_PYLK: C1.2 C2.2 C7.2 C8.2 C9.2 C10.2 C17.2 C19.2 C20.2 C21.2 C22.2 CN2.2 LED1.1 R15.2 R26.1 R34.2 R35.2 U1.1 U2.1 U5.1 U7.1 U8.1 U9.2 U10.1 U12.1 U13.5 U14.1 U15.9 U15.24 U15.48 U17.3 U17.7 U17.8 | length 7948.8
  Top Layer w10: v2(544.16,1260.63) 548.42,1260.63 563.53,1245.52 U12.1@563.53,1216.69 ; C20.2@765,1030 C20.2@769.66,1034.66 ; C21.2@1324,854.12 v2(1324,885)
  Top Layer w11: v2@809,1035 855.73,988.27 U15.24@855.73,947.32 ; U15.48@1072.27,612.68 1072.27,590.61 1072.45,590.42 1097.23,590.42 1152.65,535 v2@1154.12,535 ; U15.9@1131.32,829.21 1229.39,829.21 1254.3,854.12 C21.2@1324,854.12
  Top Layer w12: v3(226.35,1183.66) 226.96,1184.27 U7.1@226.96,1216.69 226.96,1237.87 240.96,1251.88 318.81,1251.88 340.67,1230.01 U8.1@340.67,1216.69 ; U14.1@452.1,1216.69 452.99,1217.58 452.12,1218.46 v2(452.12,1246.39) ; C20.2@769.66,1034.66 770.99,1035.99 809.99,1035.99 v2(812.28,1038.28) ; v2(1367.73,1222.03) 1368.06,1221.69 U2.1@1388.62,1221.69 ; v2(1481,1221.9) 1481.21,1221.69 U1.1@1500.05,1221.69 ; v3(1602.01,1181.02) 1611.47,1190.48 U5.1@1611.47,1221.69 1610.58,1220.8 U5.1@1610.8,1220.58 ; v2(1704,995) U17.3@1704,1060 1708.01,1064.01 1708.01,1141.25 v2(1708.87,1142.11) ; 1716.76,1150 C17.2@1748,1150 ; R34.2@1739,740 1754,755 v2(1754,775) U17.7@1754,830 1754,890 1764,900 1794,900 1804,890 U17.8@1804,830
  Top Layer w15: LED1.1@285.02,111.18 292.48,111.18 292.48,111.66 301.14,120.32 320.03,120.32 343.3,143.59 412.8,143.59 ; v2(1708.87,1142.11) 1716.76,1150 1722.9,1156.14 U10.1@1722.9,1221.69
  Top Layer w20: v2@1153.87,537.59 C19.2@1191.87,537.59
  Top Layer w30: R15.2@1789.77,458 v2@1789.77,501
  Bottom Layer w12: v2(812.28,1038.28) 1280.72,1038.28 1324,995 ; v2(1324,885) 1324,990 ; v2(1754,775) 1786.77,775 1787.77,774
  Bottom Layer w15: C9.2@272.64,1239.34 445.07,1239.34 v2(452.12,1246.39) 455.92,1242.6 521.3,1242.6 C10.2@528,1235.9 528,1244.47 v2(544.16,1260.63) v2@542.56,1262.22 ; 1197.6,547.82 R35.2@1197.6,600.62 ; v2(1367.73,1222.03) 1561,1222.03 v3(1602.01,1181.02) 1609.73,1173.3 C8.2@1647.9,1173.3 ; C8.2@1657.32,1163.88 1687.1,1163.88 v2(1708.87,1142.11)
  Bottom Layer w20: v3(226.35,1183.66) 223.47,1186.55 223.47,1203.12 C9.2@256.25,1235.9 ; C9.2@269.2,1235.9 248.4,1235.9 ; C9.2@269.2,1244.2 256.7,1244.2 248.4,1235.9 ; 504.3,146.25 386.88,28.84 271.16,28.84 121,179 121,1169.68 187.22,1235.9 248.4,1235.9 ; v2(1150.39,538) 1190.65,538 ; C22.2@1195.74,485.58 1195.74,538 ; 1197.6,547.82 R26.1@1205.59,539.83
  Bottom Layer w30: v4(424,205) 424.96,204.04 424.96,179.91 458.61,146.25 504.3,146.25 701.14,146.25 762.2,207.32 1214.96,207.32 ; 1190.65,535.41 1190.65,538 1190.65,539.83 ; C22.2@1195.74,485.58 1195.37,485.58 1195.37,447.57 1212.95,430 1281,430 CN2.2@1347,364 1347,212.32 1352,207.32 ; v4(1214,145) 1214.96,145.96 1214.96,207.32 ; 1324,995 v2(1704,995) 1737.96,995 1787.77,945.19 1787.77,774 v2(1787.77,503) 1787.77,266.91 1728.17,207.32 1352,207.32 ; 1214.96,207.32 1352,207.32
3V3_USB_PYLK: C6.2 JP1.1 U13.1 | length 2404.2
  Top Layer w20: v6@344.8,80 389.03,35.77 v6(479.96,35.77)
  Bottom Layer w20: v6(344,80) 344,85.41 334.27,95.14 334.27,100.98 199.1,236.16 199.1,895.86 274.6,971.36 473.6,971.36 517.24,1015 519,1015 532.24,1028.24 JP1.1@532.24,1030 ; v6(479.96,35.77) 486.82,28.91 1337.91,28.91 v4(1424,115) v4@1425.78,113.22
5V: C46.2 C49.2 D1.1 D2.1 D3.1 F2.1 U19.5 U21.5 | length 2231.2
  Bottom Layer w20: U19.5@275.5,4446 275.5,4355.5 C46.2@275,4355 275,4275 435.76,4114.24 609,4114.24 ; U21.5@1650.5,4422 1650.5,4344.5 C49.2@1651,4344
  Bottom Layer w30: F2.1@838.02,3898 763,3898 609,4052 609,4114.24 609,4176.47 623.53,4191 D1.1@639.75,4191 789,4191 859.05,4261.05 901.47,4261.05 916,4275.57 D2.1@916,4280.75 1024,4280.75 D3.1@1025,4279.75 1098.25,4279.75 1157,4221 1523,4221 1646,4344 C49.2@1651,4344
5V_OUT_EN: R28.1 U15.11 | length 1065.3
  Top Layer w6: R28.1@234,535 234,560 284.65,610.65 543.42,610.65 654.92,722.16 v2(654.92,728.42) ; v2(1037.27,804.07) 1037.27,821.87 1083.98,868.58 U15.11@1131.32,868.58
  Bottom Layer w6: v2(654.92,728.42) 963.41,728.42 1037.27,802.29 v2(1037.27,804.07)
5V_USB1_START: C47.2 JP5.1 R47.2 R48.2 R60.2 U19.1 USB1.A4 USB1.A9 USB1.B4 USB1.B9 | length 2064.5
  Top Layer w8: v1(632,3756) 677,3801 677,3864 643,3898 643,4037 JP5.1@694,4088
  Top Layer w30: JP5.1@694,4088 796.48,4190.48 v4(796.48,4313.99)
  Bottom Layer w8: R60.2@409,3261 455,3261 632,3438 v1(632,3756) ; R47.2@574,4359.99 585.38,4348.61 585.38,4336.12 v4(607.5,4314) ; v4(796.48,4313.99) 796.48,4344.48 R48.2@812,4360
  Bottom Layer w20: U19.1@275.5,4546 275.5,4510.5 295,4491 399,4491 436,4454 C47.2@436,4449
  Bottom Layer w30: C47.2@436,4449 436,4376 498,4314 v4(607.5,4314) ; v4(607.5,4314) v4(796.48,4313.99)
5V_USB2_START: C51.2 JP6.1 R65.2 R66.2 R85.2 U21.1 USB2.A4 USB2.A9 USB2.B4 USB2.B9 | length 3420.9
  Top Layer w30: JP6.1@1068,4087 1190.5,4209.5 v4(1190.5,4314)
  Bottom Layer w8: R65.2@1156,4360 1166.74,4349.26 1166.74,4337.76 v4(1190.5,4314) ; v4(1379.48,4313.99) 1379.48,4316.48 1395,4332 R66.2@1395,4360 ; R85.2@1552.31,2564.31 1558,2570 1558,2589 1579,2610 1838,2610 1911,2683 1911,4194.47 1818,4287.47 1818,4424.83 1772.83,4470 1687.5,4470 1650.5,4507 U21.1@1650.5,4522
  Bottom Layer w20: C51.2@1582,4524 1584,4522 U21.1@1650.5,4522
  Bottom Layer w30: v4(1190.5,4314) v4(1379.48,4313.99) 1485.99,4313.99 1582,4410 C51.2@1582,4524
5V_USB_CHGR: 5V_USB_CHGR.1 C3.2 C4.2 F1.2 U9.3 U16.5 | length 810
  Top Layer w20: 5V_USB_CHGR.1@207,607 207,604.29 183.4,580.69 183.4,448.1 211.5,420 U16.5@211.5,413.09 ; U16.5@211.5,405 U16.5@211.5,413.09 ; v5(239,415) 237.09,413.09 U16.5@211.5,413.09
  Bottom Layer w30: v5(239,415) 269,445 F1.2@547.02,445 547.02,269.37 504,226.35 v4(504,225)
5V_USB_PYLK: C15.2 D1.2 JP1.3 U16.1 | length 5006.4
  Top Layer w20: v4(158,1137) 158,1141.06 147.1,1151.96 147.1,1366.24 v4(275,1494.14) 274.89,1494.25 274.89,1587.08 v4(274,1587.97) 271.53,1590.44 271.53,1612.68 232.74,1651.46 166.5,1651.46 100.9,1717.06 100.9,4183.88 162.35,4245.34 306.66,4245.34 360,4192 v4(492,4192) ; v5(176.39,196.82) 177.3,195.91 223.09,195.91 C15.2@224,195 ; U16.1@211.5,304.69 211.5,290 211.19,289.69 211.19,210 C15.2@224,210
  Bottom Layer w20: v4(158,1137) 207.03,1087.97 207.03,969 ; v5(176.39,196.82) 173.92,197.32 170.21,201.03 168.81,202.43 159.92,215.77 159.92,921.89 207.03,969 ; JP1.3@334,1030 330.18,1033.82 271.85,1033.82 207.03,969 ; v4(492,4192) D1.2@546.25,4192
AD_TVDD: R16.1 R20.2 U15.19 | length 586.3
  Top Layer w6: R20.2@500.52,833.7 R16.1@500.52,882.61 557.79,882.61 622.97,947.79 798.66,947.79 842.59,903.86 945.86,903.86 954.16,912.17 U15.19@954.16,947.32
BOOT0: CN5.6 R41.2 U18.95 | length 1486.9
  Top Layer w8: CN5.6@165,1961 171.4,1961 220.26,2009.86 291.93,2009.86 579.48,2297.41 579.48,2607.6 U18.95@860.26,2888.38
  Bottom Layer w8: CN5.6@165,1961 216,1910 299,1910 R41.2@349,1960
DIR_RESET: U10.5 U15.3 | length 1394.4
  Top Layer w5: U15.3@1131.32,711.1 1219.66,711.1 1259.03,671.73 1333,597.76 1333,573.99 1396.78,510.22 1547.12,510.22 1603.53,566.63 1603.53,1074.04 1695.97,1166.47 1695.97,1238.45 1744.1,1286.59 1744.1,1303.92 U10.5@1748.49,1308.31
DIR_RTCK_DTR: U5.5 U15.4 | length 1362.6
  Top Layer w5: U15.4@1131.32,730.79 1222.69,730.79 1262.06,691.42 1350,603.48 1350,576.92 1398.09,528.83 1534.95,528.83 1587.53,581.41 1587.53,1078.32 1682.97,1173.76 1682.97,1245.09 1641.45,1286.6 1641.45,1303.92 U5.5@1637.06,1308.31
